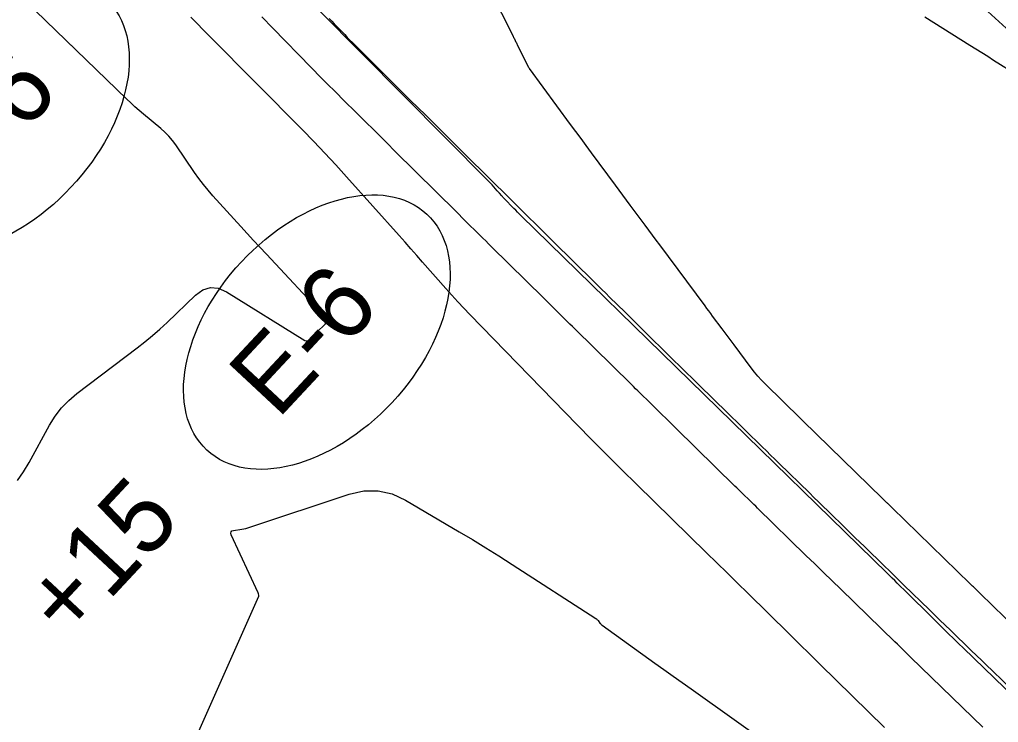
# Model space of a CAD drawing. Extents: x 1005228 to 1008882, y 1883389 to 1885754.
# Drawn here: x 1007083.3 to 1007166.4, y 1885273.6 to 1885333.3 of the extents above; entities that cross this region are included whole.
import ezdxf

# ---------------------------------------------------------------- set-up
doc = ezdxf.new("R2010")
doc.units = 0
for name, color, linetype in [('C-ANNO-NOTE', 7, 'Continuous'), ('R_Erosion', 7, 'Continuous'), ('S_BASELINE', 7, 'Continuous'), ('TSOBSTACLE', 7, 'Continuous')]:
    doc.layers.add(name, color=color, linetype=linetype)

msp = doc.modelspace()

# ---------------------------------------------------------------- linework, layer by layer
at = {"layer": 'C-ANNO-NOTE'}
for points in [[(1007189.171, 1885255.049), (1007164.33, 1885279.042), (1007164.012, 1885279.35), (1007163.694, 1885279.66), (1007163.376, 1885279.97), (1007163.06, 1885280.28), (1007161.68, 1885281.638), (1007161.421, 1885281.893), (1007161.163, 1885282.147), (1007160.904, 1885282.402), (1007160.646, 1885282.656), (1007158.664, 1885284.606), (1007157.803, 1885285.453), (1007157.587, 1885285.665), (1007157.372, 1885285.876), (1007157.156, 1885286.088), (1007156.94, 1885286.299), (1007125.869, 1885316.648), (1007125.711, 1885316.803), (1007125.553, 1885316.96), (1007125.397, 1885317.118), (1007125.241, 1885317.276), (1007124.414, 1885318.126), (1007124.363, 1885318.179), (1007124.313, 1885318.233), (1007124.264, 1885318.287), (1007124.215, 1885318.342), (1007124.022, 1885318.563), (1007123.974, 1885318.618), (1007123.925, 1885318.673), (1007123.876, 1885318.728), (1007123.827, 1885318.783), (1007123.389, 1885319.271), (1007123.3, 1885319.37), (1007123.208, 1885319.468), (1007123.116, 1885319.565), (1007123.023, 1885319.661), (1007105.132, 1885337.718)], [(1007186.684, 1885314.765), (1007162.389, 1885336.878)], [(1007083.068, 1885294.182), (1007083.589, 1885294.912), (1007084.054, 1885295.686), (1007085.797, 1885298.869), (1007086.269, 1885299.633), (1007086.813, 1885300.336), (1007087.428, 1885300.977), (1007088.116, 1885301.556), (1007093.232, 1885305.429), (1007093.891, 1885305.943), (1007094.535, 1885306.476), (1007095.163, 1885307.028), (1007095.776, 1885307.597), (1007098.194, 1885309.913), (1007098.812, 1885310.365), (1007099.457, 1885310.561), (1007100.128, 1885310.503), (1007100.827, 1885310.19), (1007107.486, 1885306.072), (1007107.582, 1885306.029), (1007107.674, 1885306.022), (1007107.762, 1885306.051), (1007107.845, 1885306.117), (1007108.169, 1885306.45), (1007108.251, 1885306.532), (1007108.334, 1885306.614), (1007108.417, 1885306.695), (1007108.502, 1885306.774), (1007109.221, 1885307.438), (1007109.334, 1885307.576), (1007109.375, 1885307.717), (1007109.344, 1885307.861), (1007109.242, 1885308.007), (1007104.215, 1885313.395), (1007103.671, 1885313.98), (1007103.129, 1885314.566), (1007102.59, 1885315.154), (1007102.052, 1885315.744), (1007099.681, 1885318.354), (1007099.265, 1885318.829), (1007098.865, 1885319.317), (1007098.482, 1885319.818), (1007098.116, 1885320.333), (1007096.51, 1885322.675), (1007096.229, 1885323.057), (1007095.923, 1885323.417), (1007095.593, 1885323.755), (1007095.239, 1885324.071), (1007093.774, 1885325.29), (1007093.411, 1885325.598), (1007093.054, 1885325.913), (1007092.703, 1885326.235), (1007092.358, 1885326.563), (1007082.886, 1885335.748)], [(1007156.712, 1885273.185), (1007151.266, 1885278.542), (1007148.633, 1885281.133), (1007145.122, 1885284.588), (1007144.243, 1885285.451), (1007143.364, 1885286.314), (1007142.485, 1885287.175), (1007141.604, 1885288.036), (1007135.675, 1885293.828), (1007134.397, 1885295.084), (1007133.127, 1885296.348), (1007131.865, 1885297.62), (1007130.611, 1885298.9), (1007121.495, 1885308.265), (1007120.976, 1885308.805), (1007120.464, 1885309.353), (1007119.959, 1885309.907), (1007119.462, 1885310.468), (1007117.487, 1885312.726), (1007116.992, 1885313.29), (1007116.496, 1885313.852), (1007115.998, 1885314.413), (1007115.498, 1885314.972), (1007111.025, 1885319.965), (1007110.107, 1885320.978), (1007109.176, 1885321.979), (1007108.232, 1885322.968), (1007107.276, 1885323.945), (1007099.373, 1885331.922), (1007097.791, 1885333.51)], [(1007098.152, 1885272.107), (1007103.569, 1885284.344), (1007103.577, 1885284.367), (1007103.581, 1885284.39), (1007103.58, 1885284.413), (1007103.576, 1885284.436), (1007103.55, 1885284.531), (1007103.544, 1885284.555), (1007103.536, 1885284.578), (1007103.527, 1885284.601), (1007103.517, 1885284.624), (1007101.235, 1885289.562), (1007101.192, 1885289.704), (1007101.211, 1885289.813), (1007101.292, 1885289.888), (1007101.433, 1885289.93), (1007102.123, 1885290.033), (1007102.295, 1885290.063), (1007102.465, 1885290.099), (1007102.633, 1885290.143), (1007102.799, 1885290.195), (1007111.258, 1885293.012), (1007112.496, 1885293.293), (1007113.706, 1885293.302), (1007114.886, 1885293.039), (1007116.038, 1885292.504), (1007120.586, 1885289.82), (1007121.72, 1885289.143), (1007122.846, 1885288.455), (1007123.966, 1885287.756), (1007125.079, 1885287.046), (1007132.193, 1885282.456), (1007132.247, 1885282.417), (1007132.297, 1885282.374), (1007132.344, 1885282.327), (1007132.387, 1885282.276), (1007132.549, 1885282.063), (1007132.591, 1885282.012), (1007132.637, 1885281.964), (1007132.686, 1885281.919), (1007132.739, 1885281.878), (1007137.222, 1885278.655), (1007137.987, 1885278.106), (1007138.754, 1885277.557), (1007139.52, 1885277.009), (1007140.288, 1885276.461), (1007155.111, 1885265.905)]]:
    msp.add_lwpolyline(points, dxfattribs=at)
at = {"layer": 'R_Erosion'}
for centre, major_axis in [((1007081.236, 1885325.059), (9.368, 9.993)), ((1007108.502, 1885306.774), (9.342, 10.017))]:
    msp.add_ellipse(centre, major_axis=major_axis, ratio=0.638788, dxfattribs=at)
at = {"layer": 'TSOBSTACLE'}
for points in [[(1007171.14, 1885278.466), (1007164.838, 1885284.575), (1007164.555, 1885284.849), (1007164.272, 1885285.123), (1007164.202, 1885285.192), (1007164.131, 1885285.26), (1007164.061, 1885285.329), (1007163.99, 1885285.398), (1007157.365, 1885291.843), (1007157.194, 1885292.009), (1007157.018, 1885292.18), (1007156.978, 1885292.219), (1007156.938, 1885292.258), (1007156.898, 1885292.297), (1007156.858, 1885292.337), (1007156.617, 1885292.572), (1007156.536, 1885292.65), (1007149.787, 1885299.241), (1007149.731, 1885299.296), (1007149.619, 1885299.405), (1007146.584, 1885302.379), (1007146.266, 1885302.702), (1007145.962, 1885303.037), (1007145.671, 1885303.383), (1007145.394, 1885303.741), (1007143.936, 1885305.696), (1007143.851, 1885305.809), (1007143.767, 1885305.923), (1007143.682, 1885306.036), (1007143.597, 1885306.15), (1007143.259, 1885306.604), (1007143.175, 1885306.717), (1007143.09, 1885306.831), (1007143.006, 1885306.944), (1007142.921, 1885307.058), (1007142.123, 1885308.133), (1007141.962, 1885308.35), (1007141.8, 1885308.567), (1007141.639, 1885308.783), (1007141.478, 1885309), (1007137.635, 1885314.173), (1007137.321, 1885314.596), (1007137.007, 1885315.018), (1007136.694, 1885315.441), (1007136.381, 1885315.865), (1007135.128, 1885317.557), (1007134.814, 1885317.98), (1007134.501, 1885318.403), (1007134.188, 1885318.827), (1007133.875, 1885319.25), (1007131.831, 1885322.012), (1007131.386, 1885322.614), (1007130.942, 1885323.216), (1007130.497, 1885323.818), (1007130.053, 1885324.42), (1007126.553, 1885329.167), (1007126.529, 1885329.2), (1007126.507, 1885329.235), (1007126.487, 1885329.27), (1007126.469, 1885329.307), (1007126.373, 1885329.507), (1007126.368, 1885329.518), (1007126.362, 1885329.529), (1007126.356, 1885329.54), (1007126.35, 1885329.551), (1007126.326, 1885329.594), (1007126.32, 1885329.605), (1007126.314, 1885329.615), (1007126.308, 1885329.626), (1007126.302, 1885329.637), (1007125.583, 1885331.095), (1007125.549, 1885331.165), (1007125.515, 1885331.234), (1007125.48, 1885331.304), (1007125.445, 1885331.373), (1007125.307, 1885331.652), (1007125.272, 1885331.721), (1007125.238, 1885331.791), (1007125.203, 1885331.86), (1007125.168, 1885331.93), (1007122.326, 1885337.614)], [(1007165.075, 1885273.209), (1007158.962, 1885279.135), (1007158.847, 1885279.246), (1007158.732, 1885279.358), (1007158.617, 1885279.47), (1007158.502, 1885279.581), (1007158.042, 1885280.029), (1007157.812, 1885280.252), (1007157.583, 1885280.476), (1007153.008, 1885284.925), (1007152.268, 1885285.645), (1007151.529, 1885286.365), (1007150.79, 1885287.086), (1007150.051, 1885287.806), (1007145.941, 1885291.819), (1007145.781, 1885291.976), (1007145.62, 1885292.132), (1007145.46, 1885292.289), (1007145.3, 1885292.445), (1007144.658, 1885293.071), (1007144.498, 1885293.228), (1007144.338, 1885293.384), (1007144.178, 1885293.541), (1007144.018, 1885293.698), (1007139.022, 1885298.593), (1007138.464, 1885299.14), (1007137.533, 1885300.052), (1007137.347, 1885300.234), (1007137.161, 1885300.417), (1007136.975, 1885300.599), (1007136.789, 1885300.782), (1007135.977, 1885301.58), (1007135.779, 1885301.774), (1007135.582, 1885301.968), (1007135.385, 1885302.162), (1007135.187, 1885302.356), (1007130.445, 1885307.017), (1007130.221, 1885307.239), (1007129.996, 1885307.46), (1007129.771, 1885307.681), (1007129.546, 1885307.903), (1007128.648, 1885308.789), (1007128.423, 1885309.011), (1007128.199, 1885309.233), (1007127.974, 1885309.454), (1007127.749, 1885309.676), (1007123.348, 1885314.018), (1007123.095, 1885314.267), (1007122.843, 1885314.516), (1007122.591, 1885314.765), (1007122.339, 1885315.014), (1007121.08, 1885316.261), (1007120.325, 1885317.008), (1007116.91, 1885320.389), (1007116.307, 1885320.986), (1007115.704, 1885321.584), (1007115.101, 1885322.182), (1007114.498, 1885322.78), (1007111.461, 1885325.797), (1007111.173, 1885326.084), (1007110.884, 1885326.371), (1007110.596, 1885326.657), (1007110.307, 1885326.944), (1007109.153, 1885328.091), (1007108.865, 1885328.378), (1007108.579, 1885328.666), (1007108.293, 1885328.956), (1007108.009, 1885329.247), (1007104.772, 1885332.58), (1007104.455, 1885332.906), (1007104.138, 1885333.233), (1007103.821, 1885333.559)], [(1007109.539, 1885333.407), (1007109.761, 1885333.179), (1007109.982, 1885332.951), (1007110.869, 1885332.038), (1007111.091, 1885331.811), (1007111.314, 1885331.584), (1007111.538, 1885331.359), (1007111.763, 1885331.134), (1007115.872, 1885327.052), (1007116.128, 1885326.797), (1007116.384, 1885326.543), (1007116.64, 1885326.288), (1007116.896, 1885326.034), (1007117.921, 1885325.016), (1007118.177, 1885324.761), (1007118.434, 1885324.507), (1007118.69, 1885324.253), (1007118.947, 1885323.999), (1007120.341, 1885322.619), (1007121.158, 1885321.81), (1007124.968, 1885318.038), (1007125.269, 1885317.741), (1007125.569, 1885317.444), (1007125.869, 1885317.147), (1007126.17, 1885316.851), (1007127.372, 1885315.664), (1007127.673, 1885315.368), (1007127.973, 1885315.071), (1007128.274, 1885314.775), (1007128.575, 1885314.478), (1007132.059, 1885311.04), (1007132.388, 1885310.716), (1007132.716, 1885310.392), (1007133.045, 1885310.069), (1007133.374, 1885309.746), (1007134.689, 1885308.453), (1007135.018, 1885308.129), (1007135.347, 1885307.806), (1007135.675, 1885307.483), (1007136.004, 1885307.16), (1007138.809, 1885304.402), (1007139.343, 1885303.878), (1007139.876, 1885303.354), (1007140.41, 1885302.83), (1007140.944, 1885302.307), (1007143.423, 1885299.878), (1007143.786, 1885299.523), (1007144.148, 1885299.167), (1007144.511, 1885298.812), (1007144.873, 1885298.457), (1007146.323, 1885297.037), (1007146.686, 1885296.682), (1007147.048, 1885296.327), (1007147.411, 1885295.972), (1007147.774, 1885295.617), (1007150.34, 1885293.112), (1007150.729, 1885292.732), (1007151.118, 1885292.352), (1007151.508, 1885291.972), (1007151.897, 1885291.592), (1007153.454, 1885290.071), (1007153.844, 1885289.691), (1007154.233, 1885289.312), (1007154.623, 1885288.932), (1007155.013, 1885288.553), (1007156.718, 1885286.895), (1007157.132, 1885286.492), (1007157.546, 1885286.089), (1007157.96, 1885285.686), (1007158.374, 1885285.283), (1007160.548, 1885283.169), (1007160.99, 1885282.739), (1007161.432, 1885282.309), (1007161.874, 1885281.88), (1007162.317, 1885281.451), (1007164.087, 1885279.734), (1007164.53, 1885279.305), (1007164.973, 1885278.876), (1007165.415, 1885278.447), (1007165.858, 1885278.018), (1007167.725, 1885276.208)], [(1007160.142, 1885333.553), (1007163.979, 1885331.142), (1007164.48, 1885330.827), (1007164.981, 1885330.513), (1007165.483, 1885330.198), (1007165.984, 1885329.884), (1007167.991, 1885328.628)]]:
    msp.add_lwpolyline(points, dxfattribs=at)

# ---------------------------------------------------------------- texts
at = {"layer": 'R_Erosion'}
for rotation, p in [(46.84988, (1007077.875, 1885317.578)), (46.99803, (1007105.16, 1885299.284))]:
    msp.add_text('E-6', height=6.2498, rotation=rotation, dxfattribs=at).set_placement(p)
at = {"layer": 'S_BASELINE'}
msp.add_text('+15', height=6.2498, rotation=46.99803, dxfattribs=at).set_placement((1007087.465, 1885280.31))

doc.saveas('drawing.dxf')
